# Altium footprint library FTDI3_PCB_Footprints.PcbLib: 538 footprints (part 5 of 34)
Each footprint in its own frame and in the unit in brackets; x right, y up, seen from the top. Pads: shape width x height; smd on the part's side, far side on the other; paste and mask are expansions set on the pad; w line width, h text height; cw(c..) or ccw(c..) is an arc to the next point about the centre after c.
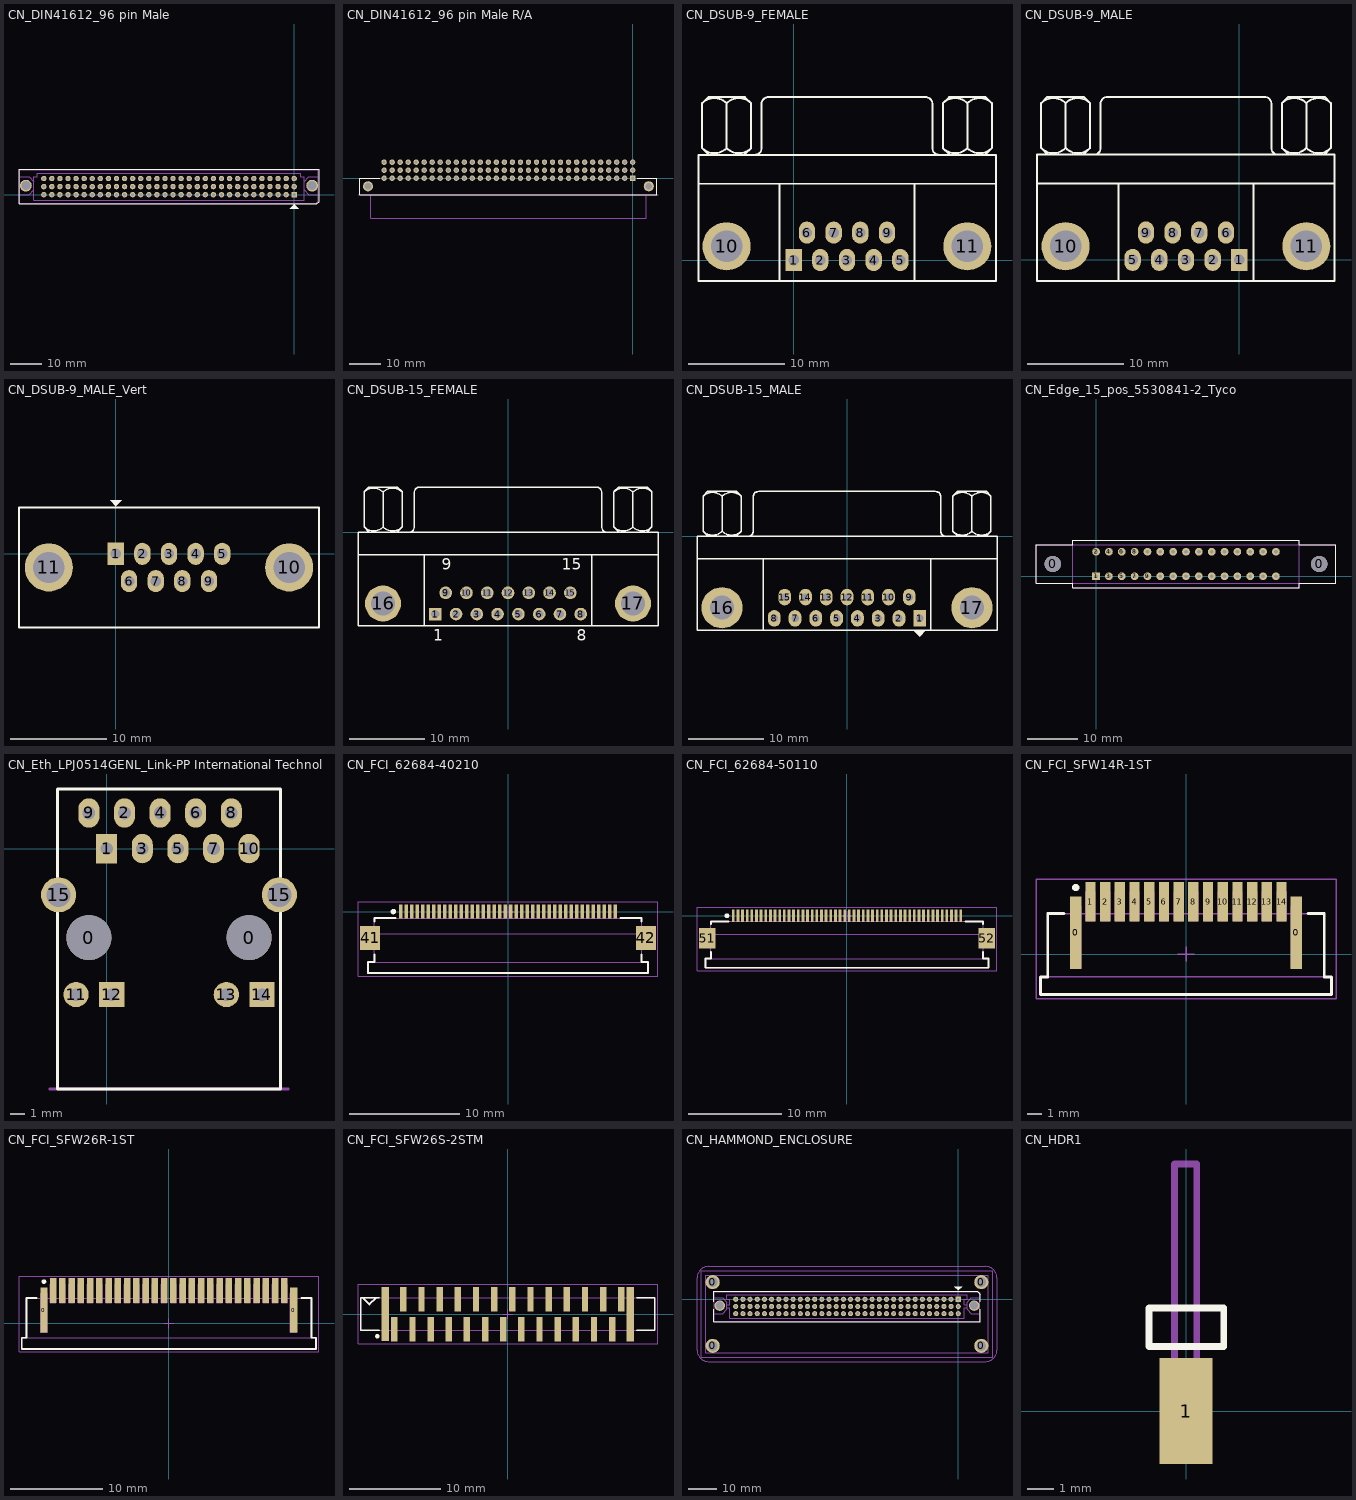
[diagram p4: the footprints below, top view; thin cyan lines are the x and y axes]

## CN_DIN41612_96 pin Male [mm] "DIN41612 series; FCI Part No. 86093967113745E1LF; Number of Positions = 95; pitch 2.54 mm"
height 15.24
pads (98):
  rect 1.7x1.7 hole 1: 1(0,0)
  round 1.7 hole 1: 2(-2.54,0) 3(-5.08,0) 4(-7.62,0) 5(-10.16,0) 6(-12.7,0) 7(-15.24,0) 8(-17.78,0) 9(-20.32,0) 10(-22.86,0) 11(-25.4,0) 12(-27.94,0) 13(-30.48,0) 14(-33.02,0) 15(-35.56,0) 16(-38.1,0) 17(-40.64,0) 18(-43.18,0) 19(-45.72,0) 20(-48.26,0) 21(-50.8,0) 22(-53.34,0) 23(-55.88,0) 24(-58.42,0) 25(-60.96,0) 26(-63.5,0) 27(-66.04,0) 28(-68.58,0) 29(-71.12,0) 30(-73.66,0) 31(-76.2,0) 32(-78.74,0) 33(0,2.54) 34(-2.54,2.54) 35(-5.08,2.54) 36(-7.62,2.54) 37(-10.16,2.54) 38(-12.7,2.54) 39(-15.24,2.54) 40(-17.78,2.54) 41(-20.32,2.54) 42(-22.86,2.54) 43(-25.4,2.54) 44(-27.94,2.54) 45(-30.48,2.54) 46(-33.02,2.54) 47(-35.56,2.54) 48(-38.1,2.54) 49(-40.64,2.54) 50(-43.18,2.54) 51(-45.72,2.54) 52(-48.26,2.54) 53(-50.8,2.54) 54(-53.34,2.54) 55(-55.88,2.54) 56(-58.42,2.54) 57(-60.96,2.54) 58(-63.5,2.54) 59(-66.04,2.54) 60(-68.58,2.54) 61(-71.12,2.54) 62(-73.66,2.54) 63(-76.2,2.54) 64(-78.74,2.54) 65(0,5.08) 66(-2.54,5.08) 67(-5.08,5.08) 68(-7.62,5.08) 69(-10.16,5.08) 70(-12.7,5.08) 71(-15.24,5.08) 72(-17.78,5.08) 73(-20.32,5.08) 74(-22.86,5.08) 75(-25.4,5.08) 76(-27.94,5.08) 77(-30.48,5.08) 78(-33.02,5.08) 79(-35.56,5.08) 80(-38.1,5.08) 81(-40.64,5.08) 82(-43.18,5.08) 83(-45.72,5.08) 84(-48.26,5.08) 85(-50.8,5.08) 86(-53.34,5.08) 87(-55.88,5.08) 88(-58.42,5.08) 89(-60.96,5.08) 90(-63.5,5.08) 91(-66.04,5.08) 92(-68.58,5.08) 93(-71.12,5.08) 94(-73.66,5.08) 95(-76.2,5.08) 96(-78.74,5.08)
  round 3.7 hole 2.8: MH1(-84.37,2.84) MH2(5.63,2.84)
Top Overlay:
  region: 0,-3.05 1.39,-4.44 -1.39,-4.44
  lines w0.254: -86.53,-2.93 7.05,-2.93 7.79,-2.19 7.79,8.01 -86.53,8.01 -86.53,-2.93
M13_Assembly_Info:
  lines w0.1: -86.35,0 -83.36,0 -81.86,1.5 ; -86.35,5.6 -83.36,5.6 -81.86,4.1 ; -81.86,4.55 -81.86,-1.69 ; -80.82,6.77 2.08,6.77 ; -80.82,6.78 -80.82,5.59 -81.86,5.59 -81.86,4.1 ; 2.08,6.78 2.08,5.59 3.12,5.59 3.12,4.1 ; 3.12,1.5 4.62,0 7.61,0 ; 3.12,4.55 3.12,-1.69 ; 7.61,5.6 4.62,5.6 3.12,4.1 ; -81.86,-1.69 3.12,-1.69 ; -81.86,-1.69 -81.86,1.4 -81.86,4.1 ; 3.12,-1.69 3.12,1.4 3.12,4.1 ; -86.35,-2.755 6.965,-2.755 7.61,-2.11 7.61,7.835 -86.35,7.835 -86.35,-2.755
  text "c32" at -80.73,6.57 h1
  text "b32" at -80.73,3.68 h1
  text "a32" at -80.72,1.05 h1
  text "a1" at 0.97,0.53 h1
  text "b1" at 0.96,3.05 h1
  text "c1" at 0.96,5.72 h1
3D body: height 11.52, standoff -3.28, extent -86.298,-2.723 7.557,7.877

## CN_DIN41612_96 pin Male R/A [mm] "DIN41612 series; FCI Part No. 86093967113745E1LF; Number of Positions = 95; pitch 2.54 mm"
height 15.24
pads (98):
  rect 1.7x1.7 hole 1: 1(0,0)
  round 1.7 hole 1: 2(-2.54,0) 3(-5.08,0) 4(-7.62,0) 5(-10.16,0) 6(-12.7,0) 7(-15.24,0) 8(-17.78,0) 9(-20.32,0) 10(-22.86,0) 11(-25.4,0) 12(-27.94,0) 13(-30.48,0) 14(-33.02,0) 15(-35.56,0) 16(-38.1,0) 17(-40.64,0) 18(-43.18,0) 19(-45.72,0) 20(-48.26,0) 21(-50.8,0) 22(-53.34,0) 23(-55.88,0) 24(-58.42,0) 25(-60.96,0) 26(-63.5,0) 27(-66.04,0) 28(-68.58,0) 29(-71.12,0) 30(-73.66,0) 31(-76.2,0) 32(-78.74,0) 33(0,2.54) 34(-2.54,2.54) 35(-5.08,2.54) 36(-7.62,2.54) 37(-10.16,2.54) 38(-12.7,2.54) 39(-15.24,2.54) 40(-17.78,2.54) 41(-20.32,2.54) 42(-22.86,2.54) 43(-25.4,2.54) 44(-27.94,2.54) 45(-30.48,2.54) 46(-33.02,2.54) 47(-35.56,2.54) 48(-38.1,2.54) 49(-40.64,2.54) 50(-43.18,2.54) 51(-45.72,2.54) 52(-48.26,2.54) 53(-50.8,2.54) 54(-53.34,2.54) 55(-55.88,2.54) 56(-58.42,2.54) 57(-60.96,2.54) 58(-63.5,2.54) 59(-66.04,2.54) 60(-68.58,2.54) 61(-71.12,2.54) 62(-73.66,2.54) 63(-76.2,2.54) 64(-78.74,2.54) 65(0,5.08) 66(-2.54,5.08) 67(-5.08,5.08) 68(-7.62,5.08) 69(-10.16,5.08) 70(-12.7,5.08) 71(-15.24,5.08) 72(-17.78,5.08) 73(-20.32,5.08) 74(-22.86,5.08) 75(-25.4,5.08) 76(-27.94,5.08) 77(-30.48,5.08) 78(-33.02,5.08) 79(-35.56,5.08) 80(-38.1,5.08) 81(-40.64,5.08) 82(-43.18,5.08) 83(-45.72,5.08) 84(-48.26,5.08) 85(-50.8,5.08) 86(-53.34,5.08) 87(-55.88,5.08) 88(-58.42,5.08) 89(-60.96,5.08) 90(-63.5,5.08) 91(-66.04,5.08) 92(-68.58,5.08) 93(-71.12,5.08) 94(-73.66,5.08) 95(-76.2,5.08) 96(-78.74,5.08)
  round 3.2 hole 2.1: MH1(-83.82,-2.54) MH2(5.08,-2.54)
Top Overlay:
  lines w0.2: -80.1,0 -86.37,0 -86.37,-5.3 7.63,-5.3 7.63,0 1.41,0
Mechanical 1:
  lines w0.2: -87,-5.3 8,-5.3
M13_Assembly_Info:
  lines w0.2: -82.97,-5.3 -82.97,-12.74 4.23,-12.74 4.23,-5.3
  text "c32" at -80.8,6.49 h1
  text "b32" at -80.8,3.71 h1
  text "a32" at -80.81,1.04 h1
  text "a1" at 1.07,0.56 h1
  text "b1" at 1.04,3.13 h1
  text "c1" at 1,5.64 h1

## CN_DSUB-9_FEMALE [mm] "Connector; D Subminiature AMPLIMITE 2000; 9 Position; Right Angle"
height 12.75
pads (11):
  rect 1.7x2.3 hole 1.09: 1(0,0)
  oval 1.7x2.3 hole 1.09: 2(2.77,0) 3(5.54,0) 4(8.31,0) 5(11.08,0) 6(1.385,2.84) 7(4.155,2.84) 8(6.925,2.84) 9(9.695,2.84)
  round 5 hole 3.26: 10(-6.955,1.42) 11(18.035,1.42)
Top Overlay:
  lines w0.2: -9.86,7.92 20.94,7.92 ; -9.498,16.27 -9.498,11.619 -8.863,10.984 ; -9.498,16.285 -8.863,16.92 -5.053,16.92 -4.418,16.285 ; -6.958,11.619 -6.958,16.27 ; -5.053,10.984 -4.418,11.619 -4.418,16.27 ; -4.418,15.006 -4.418,15.218 ; -4.02,10.925 ccw(c-4.02,11.62) -3.325,11.62 -3.325,16.22 ; -3.32,16.225 cw(c-2.625,16.225) -2.625,16.92 13.705,16.92 cw(c13.705,16.225) 14.4,16.225 ; -1.46,-2.175 -1.46,7.92 ; 12.54,-2.175 12.54,7.92 ; 14.405,16.22 14.405,11.62 ccw(c15.1,11.62) 15.1,10.925 ; 15.502,16.27 15.502,11.619 16.137,10.984 ; 15.502,16.285 16.137,16.92 19.947,16.92 20.582,16.285 ; 18.042,11.619 18.042,16.27 ; 19.947,10.984 20.582,11.619 20.582,16.27 ; 20.582,15.006 20.582,15.218 ; -9.86,-2.175 21.025,-2.175 21.025,10.92 -9.86,10.92 -9.86,-2.175
  lines w0.203: -9.5,11.617 ccw(c-8.228,12.889) -6.956,11.617 ; -9.498,16.27 cw(c-8.226,14.998) -6.953,16.27 ; -6.962,16.27 cw(c-5.69,14.998) -4.418,16.27 ; -6.96,11.617 ccw(c-5.688,12.889) -4.416,11.617 ; 15.5,11.617 ccw(c16.772,12.889) 18.044,11.617 ; 15.502,16.27 cw(c16.774,14.998) 18.047,16.27 ; 18.038,16.27 cw(c19.31,14.998) 20.582,16.27 ; 18.04,11.617 ccw(c19.312,12.889) 20.584,11.617
3D body: height 12.44, standoff 0.02, extent -9.975,-2.275 21.125,16.715

## CN_DSUB-9_MALE [mm] "Connector; D Subminiature AMPLIMITE 2000; 9 Position; Right Angle"
height 12.75
pads (11):
  rect 1.7x2.3 hole 1.09: 1(0,0)
  oval 1.7x2.3 hole 1.09: 2(-2.77,0) 3(-5.54,0) 4(-8.31,0) 5(-11.08,0) 6(-1.385,2.84) 7(-4.155,2.84) 8(-6.925,2.84) 9(-9.695,2.84)
  round 5 hole 3.26: 10(-18.035,1.42) 11(6.955,1.42)
Top Overlay:
  lines w0.2: -20.94,7.92 9.86,7.92 ; -20.578,16.27 -20.578,11.619 -19.943,10.984 ; -20.578,16.285 -19.943,16.92 -16.133,16.92 -15.498,16.285 ; -18.038,11.619 -18.038,16.27 ; -16.133,10.984 -15.498,11.619 -15.498,16.27 ; -15.498,15.006 -15.498,15.218 ; -15.1,10.925 ccw(c-15.1,11.62) -14.405,11.62 -14.405,16.22 ; -14.4,16.225 cw(c-13.705,16.225) -13.705,16.92 2.625,16.92 cw(c2.625,16.225) 3.32,16.225 ; -12.54,-2.2 -12.54,7.92 ; 1.46,-2.2 1.46,7.92 ; 3.325,16.22 3.325,11.62 ccw(c4.02,11.62) 4.02,10.925 ; 4.422,16.27 4.422,11.619 5.057,10.984 ; 4.422,16.285 5.057,16.92 8.867,16.92 9.502,16.285 ; 6.962,11.619 6.962,16.27 ; 8.867,10.984 9.502,11.619 9.502,16.27 ; 9.502,15.006 9.502,15.218 ; -21.025,-2.2 9.875,-2.2 9.875,10.92 -21.025,10.92 -21.025,-2.2
  lines w0.203: -20.58,11.617 ccw(c-19.308,12.889) -18.036,11.617 ; -20.578,16.27 cw(c-19.306,14.998) -18.033,16.27 ; -18.042,16.27 cw(c-16.77,14.998) -15.498,16.27 ; -18.04,11.617 ccw(c-16.768,12.889) -15.496,11.617 ; 4.42,11.617 ccw(c5.692,12.889) 6.964,11.617 ; 4.422,16.27 cw(c5.694,14.998) 6.967,16.27 ; 6.958,16.27 cw(c8.23,14.998) 9.502,16.27 ; 6.96,11.617 ccw(c8.232,12.889) 9.504,11.617
3D body: height 12.44, standoff 0.02, extent -21.125,-2.3 9.975,16.98

## CN_DSUB-9_MALE_Vert [mm] "Connector; D Subminiature AMPLIMITE 2000; 9 Position; Vertical"
height 12.75
pads (11):
  rect 1.7x2.3 hole 1.09: 1(0,0)
  oval 1.7x2.3 hole 1.09: 2(2.77,0) 3(5.54,0) 4(8.31,0) 5(11.08,0) 6(1.385,-2.84) 7(4.155,-2.84) 8(6.925,-2.84) 9(9.695,-2.84)
  round 5 hole 3.26: 10(18.035,-1.42) 11(-6.955,-1.42)
Top Overlay:
  region: 0.015,4.95 0.614,5.55 -0.589,5.55
  lines w0.2: -10.06,-7.67 21.14,-7.67 21.14,4.83 -10.06,4.83 -10.06,-7.67

## CN_DSUB-15_FEMALE [mm] "Connector; D Subminiature; 15 Position; Right Angle; Female"
height 12.75
pads (17):
  rect 1.69x1.69 hole 1.09: 1(-9.695,-10.92)
  round 1.69 hole 1.09: 2(-6.925,-10.92) 3(-4.155,-10.92) 4(-1.385,-10.92) 5(1.385,-10.92) 6(4.155,-10.92) 7(6.925,-10.92) 8(9.695,-10.92) 9(-8.31,-8.08) 10(-5.54,-8.08) 11(-2.77,-8.08) 12(0,-8.08) 13(2.77,-8.08) 14(5.54,-8.08) 15(8.31,-8.08)
  round 4.8 hole 3.18: 16(-16.66,-9.5) 17(16.66,-9.5)
Top Overlay:
  lines w0.2: -20,-3 20,-3 ; -19.188,5.35 -19.188,0.699 -18.553,0.064 ; -19.188,5.365 -18.553,6 -14.743,6 -14.108,5.365 ; -16.648,0.699 -16.648,5.35 ; -14.743,0.064 -14.108,0.699 -14.108,5.35 ; -14.108,4.086 -14.108,4.298 ; -13.195,0.005 ccw(c-13.195,0.7) -12.5,0.7 -12.5,5.3 ; -12.495,5.305 cw(c-11.8,5.305) -11.8,6 11.8,6 cw(c11.8,5.305) 12.495,5.305 ; -11.14,-12.5 -11.14,-3 ; 11.14,-12.5 11.14,-3 ; 12.5,5.3 12.5,0.7 ccw(c13.195,0.7) 13.195,0.005 ; 14.112,5.35 14.112,0.699 14.747,0.064 ; 14.112,5.365 14.747,6 18.557,6 19.192,5.365 ; 16.652,0.699 16.652,5.35 ; 18.557,0.064 19.192,0.699 19.192,5.35 ; 19.192,4.086 19.192,4.298 ; -20,-12.5 20,-12.5 20,0 -20,0 -20,-12.5
  lines w0.203: -19.19,0.697 ccw(c-17.918,1.969) -16.646,0.697 ; -19.188,5.35 cw(c-17.916,4.078) -16.643,5.35 ; -16.652,5.35 cw(c-15.38,4.078) -14.108,5.35 ; -16.65,0.697 ccw(c-15.378,1.969) -14.106,0.697 ; 14.11,0.697 ccw(c15.382,1.969) 16.654,0.697 ; 14.112,5.35 cw(c15.384,4.078) 16.657,5.35 ; 16.648,5.35 cw(c17.92,4.078) 19.192,5.35 ; 16.65,0.697 ccw(c17.922,1.969) 19.194,0.697
  text "9" at -8.81,-4.975 h1.5
  text "15" at 7.185,-4.975 h1.5
  text "8" at 9.195,-14.475 h1.5
  text "1" at -9.945,-14.475 h1.5

## CN_DSUB-15_MALE [mm] "Connector; D Subminiature; 15 Position; Right Angle; Male"
height 12.75
pads (17):
  rect 1.7x2.2 hole 1: 1(9.695,-10.92)
  oval 1.7x2.2 hole 1: 2(6.925,-10.92) 3(4.155,-10.92) 4(1.385,-10.92) 5(-1.385,-10.92) 6(-4.155,-10.92) 7(-6.925,-10.92) 8(-9.695,-10.92) 9(8.31,-8.08) 10(5.54,-8.08) 11(2.77,-8.08) 12(0,-8.08) 13(-2.77,-8.08) 14(-5.54,-8.08) 15(-8.31,-8.08)
  round 5.5 hole 3.2: 16(-16.66,-9.5) 17(16.66,-9.5)
Top Overlay:
  region: 10.53,-12.515 9.7,-13.345 9.69,-13.345 8.85,-12.505
  lines w0.2: -20,-3 20,-3 ; -19.188,5.35 -19.188,0.699 -18.553,0.064 ; -19.188,5.365 -18.553,6 -14.743,6 -14.108,5.365 ; -16.648,0.699 -16.648,5.35 ; -14.743,0.064 -14.108,0.699 -14.108,5.35 ; -14.108,4.086 -14.108,4.298 ; -13.195,0.005 ccw(c-13.195,0.7) -12.5,0.7 -12.5,5.3 ; -12.495,5.305 cw(c-11.8,5.305) -11.8,6 11.8,6 cw(c11.8,5.305) 12.495,5.305 ; -11.14,-12.5 -11.14,-3 ; 11.14,-12.5 11.14,-3 ; 12.5,5.3 12.5,0.7 ccw(c13.195,0.7) 13.195,0.005 ; 14.112,5.35 14.112,0.699 14.747,0.064 ; 14.112,5.365 14.747,6 18.557,6 19.192,5.365 ; 16.652,0.699 16.652,5.35 ; 18.557,0.064 19.192,0.699 19.192,5.35 ; 19.192,4.086 19.192,4.298 ; -20,-12.5 20,-12.5 20,0 -20,0 -20,-12.5
  lines w0.203: -19.19,0.697 ccw(c-17.918,1.969) -16.646,0.697 ; -19.188,5.35 cw(c-17.916,4.078) -16.643,5.35 ; -16.652,5.35 cw(c-15.38,4.078) -14.108,5.35 ; -16.65,0.697 ccw(c-15.378,1.969) -14.106,0.697 ; 14.11,0.697 ccw(c15.382,1.969) 16.654,0.697 ; 14.112,5.35 cw(c15.384,4.078) 16.657,5.35 ; 16.648,5.35 cw(c17.92,4.078) 19.192,5.35 ; 16.65,0.697 ccw(c17.922,1.969) 19.194,0.697

## CN_Edge_15_pos_5530841-2_Tyco [mil] "Card Edge connector; 15 pos; 0.1\" (2.54mm) pitch; 5530841-2 Tyco Electronics Corporation"
height 609.84
pads (32):
  round 127.95 hole 127.95 unplated: 0(-337.4,95.47) 0(1737.4,95.47)
  rect 60x60 hole 30: 1(0,0)
  round 60 hole 30: 2(0,190.94) 3(100,0) 4(100,190.94) 5(200,0) 6(200,190.94) 7(300,0) 8(300,190.94) 9(400,0) 10(400,190.94) 11(500,0) 12(500,190.94) 13(600,0) 14(600,190.94) 15(700,0) 16(700,190.94) 17(800,0) 18(800,190.94) 19(900,0) 20(900,190.94) 21(1000,0) 22(1000,190.94) 23(1100,0) 24(1100,190.94) 25(1200,0) 26(1200,190.94) 27(1300,0) 28(1300,190.94) 29(1400,0) 30(1400,190.94)
Top Overlay:
  lines w7.87: -467.72,-54.72 -467.72,245.67 -179.92,245.67 -179.92,279.53 1579.92,279.53 1579.92,245.67 1867.72,245.67 1867.72,-54.72 1579.92,-54.72 1579.92,-88.58 -179.92,-88.58 -179.92,-54.72 -467.72,-54.72
M13_Assembly_Info:
  lines w3.94: -467.52,-54.53 1867.52,-54.53 1867.52,245.47 -467.52,245.47 -467.52,-54.53 ; -179.92,-88.58 1579.92,-88.58 1579.92,279.53 -179.92,279.53 -179.92,-88.58
3D body: height 250, standoff 0, extent -467.52,-54.53 1867.52,245.47

## CN_Eth_LPJ0514GENL_Link-PP International Technology [mm] "RJ45 Ethernet Connector; PoE compatible; with magnetics and LEDs; Link-PP International Technology Co. Ltd."
height 13.4
pads (18):
  round 3.2 hole 3.2 unplated: 0(-1.27,-6.35) 0(10.16,-6.35)
  rect 1.5x2.1 hole 0.9: 1(0,0)
  oval 1.5x2.1 hole 0.9: 2(1.27,2.54) 3(2.54,0) 4(3.81,2.54) 5(5.08,0) 6(6.35,2.54) 7(7.62,0) 8(8.89,2.54) 9(-1.27,2.54) 10(10.16,0)
  round 1.8 hole 0.9: 11(-2.185,-10.414) 13(8.535,-10.414)
  rect 1.8x1.8 hole 0.9: 12(0.355,-10.414) 14(11.075,-10.414)
  round 2.5 hole 1.7: 15(-3.43,-3.302) 15(12.32,-3.302)
Top Overlay:
  lines w0.2: -3.505,-17.145 12.395,-17.145 12.395,4.25 -3.505,4.25 -3.505,-17.145
M13_Assembly_Info:
  lines w0.2: -4.055,-17.15 12.945,-17.15
  text "A" at -2.49,-9.449 h0.9
  text "K" at 0.075,-9.449 h0.9
  text "K" at 10.795,-9.449 h0.9
  text "A" at 8.23,-9.449 h0.9
  text "Yellow" at 8.231,-12.395 h0.9
  text "Green" at -2.489,-12.395 h0.9
3D body: height 13.5, standoff 0, extent -3.505,-17.145 12.395,4.25

## CN_FCI_62684-40210 [mm] "FPC/FFC Connector; 62684-40210; 40 Positions; 0.5mm Pitch Top Contact; FCI"
height 2
pads (42):
  rect 0.3x1.3 smd: 1(-9.75,0) 2(-9.25,0) 3(-8.75,0) 4(-8.25,0) 5(-7.75,0) 6(-7.25,0) 7(-6.75,0) 8(-6.25,0) 9(-5.75,0) 10(-5.25,0) 11(-4.75,0) 12(-4.25,0) 13(-3.75,0) 14(-3.25,0) 15(-2.75,0) 16(-2.25,0) 17(-1.75,0) 18(-1.25,0) 19(-0.75,0) 20(-0.25,0) 21(0.25,0) 22(0.75,0) 23(1.25,0) 24(1.75,0) 25(2.25,0) 26(2.75,0) 27(3.25,0) 28(3.75,0) 29(4.25,0) 30(4.75,0) 31(5.25,0) 32(5.75,0) 33(6.25,0) 34(6.75,0) 35(7.25,0) 36(7.75,0) 37(8.25,0) 38(8.75,0) 39(9.25,0) 40(9.75,0)
  rect 1.8x2.2 smd: 41(-12.55,-2.4) 42(12.55,-2.4)
Top Overlay:
  circle w0.25: c-10.425,0 r0.125
  lines w0.2: -12.15,-3.9 -12.15,-4.6 -12.75,-4.6 -12.75,-5.6 12.75,-5.6 12.75,-4.6 12.15,-4.6 12.15,-3.9 ; -12.15,-0.9 -12.15,-0.6 -10.25,-0.6 ; 10.25,-0.6 12.15,-0.6 12.15,-0.9
M13_Assembly_Info:
  lines w0.1: -12.15,-2 12.15,-2 ; -12.15,-4.6 -12.15,-0.6 12.15,-0.6 12.15,-4.6 12.75,-4.6 ; -12.15,-4.6 -12.75,-4.6 -12.75,-5.6 12.75,-5.6 12.75,-4.6 ; -12.15,-4.6 12.75,-4.6
  lines w0.2: -12.15,-2.9 -12.75,-2.9 -12.75,-1.9 -12.15,-1.9 ; 12.19,-2.9 12.79,-2.9 12.79,-1.9 12.19,-1.9
M15_Country_Yard:
  lines w0.1: -13.65,-5.9 -13.65,0.9 13.64,0.9 13.64,-5.9 -13.65,-5.9 ; -0.55,0 0.55,0 -0.55,0 ; 0,-0.5 0,0.5 0,-0.5
3D body: height 0, standoff 0, extent -12.75,-5.6 12.75,-0.6

## CN_FCI_62684-50110 [mm] "FPC/FFC Connector; 62684-50110; 50 Position; 0.5mm Spaced Bottom Contact; FCI"
height 2
pads (52):
  rect 0.3x1.3 smd: 1(-12.25,0) 2(-11.75,0) 3(-11.25,0) 4(-10.75,0) 5(-10.25,0) 6(-9.75,0) 7(-9.25,0) 8(-8.75,0) 9(-8.25,0) 10(-7.75,0) 11(-7.25,0) 12(-6.75,0) 13(-6.25,0) 14(-5.75,0) 15(-5.25,0) 16(-4.75,0) 17(-4.25,0) 18(-3.75,0) 19(-3.25,0) 20(-2.75,0) 21(-2.25,0) 22(-1.75,0) 23(-1.25,0) 24(-0.75,0) 25(-0.25,0) 26(0.25,0) 27(0.75,0) 28(1.25,0) 29(1.75,0) 30(2.25,0) 31(2.75,0) 32(3.25,0) 33(3.75,0) 34(4.25,0) 35(4.75,0) 36(5.25,0) 37(5.75,0) 38(6.25,0) 39(6.75,0) 40(7.25,0) 41(7.75,0) 42(8.25,0) 43(8.75,0) 44(9.25,0) 45(9.75,0) 46(10.25,0) 47(10.75,0) 48(11.25,0) 49(11.75,0) 50(12.25,0)
  rect 1.8x2.2 smd: 51(-15.05,-2.4) 52(15.05,-2.4)
Top Overlay:
  circle w0.25: c-12.925,0 r0.125
  lines w0.2: -14.65,-3.9 -14.65,-4.6 -15.25,-4.6 -15.25,-5.6 15.25,-5.6 15.25,-4.6 14.65,-4.6 14.65,-3.9 ; -14.65,-0.9 -14.65,-0.6 -12.75,-0.6 ; 12.75,-0.6 14.65,-0.6 14.65,-0.9
M13_Assembly_Info:
  lines w0.1: -14.65,-2 14.65,-2 ; -12.75,-2 12.75,-2 ; -14.65,-4.6 -14.65,-0.6 14.65,-0.6 14.65,-4.6 ; -14.65,-4.6 -15.25,-4.6 -15.25,-5.6 15.25,-5.6 15.25,-4.6 14.65,-4.6 ; -14.65,-4.6 14.65,-4.6
  lines w0.2: -14.65,-2.9 -15.25,-2.9 -15.25,-1.9 -14.65,-1.9 ; 14.65,-2.9 15.25,-2.9 15.25,-1.9 14.65,-1.9
M15_Country_Yard:
  lines w0.1: -0.55,0 0.55,0 ; 0,-0.5 0,0.5 ; -16.15,-5.9 -16.15,0.9 16.15,0.9 16.15,-5.9 -16.15,-5.9
3D body: height 0, standoff 0, extent -15.25,-5.6 15.25,-0.6

## CN_FCI_SFW14R-1ST [mm] "FPC/FFC Connector; SFW14R-1ST; 14 Positions; 1.0mm Spaced Bottom Contact; FCI"
height 2
pads (16):
  rect 0.8x4.9 smd: 0(-7.5,1.45) 0(7.5,1.45)
  rect 0.7x2.7 smd: 1(-6.5,3.55) 2(-5.5,3.55) 3(-4.5,3.55) 4(-3.5,3.55) 5(-2.5,3.55) 6(-1.5,3.55) 7(-0.5,3.55) 8(0.5,3.55) 9(1.5,3.55) 10(2.5,3.55) 11(3.5,3.55) 12(4.5,3.55) 13(5.5,3.55) 14(6.5,3.55)
Top Overlay:
  circle w0.25: c-7.5,4.525 r0.125
  lines w0.2: -8.3,2.75 -9.4,2.75 -9.4,-1.55 -9.9,-1.55 -9.9,-2.75 9.9,-2.75 9.9,-1.55 9.4,-1.55 9.4,2.75 8.3,2.75
M13_Assembly_Info:
  lines w0.1: -9.4,-1.55 -9.4,2.75 9.4,2.75 9.4,-1.55 ; -9.9,-2.75 -9.9,-1.55 9.9,-1.55 9.9,-2.75 -9.9,-2.75 ; -7.85,-0.95 -7.85,3.25 -7.15,3.25 -7.15,-0.95 -7.85,-0.95 ; -6.8,2.25 -6.8,4.25 -6.2,4.25 -6.2,2.25 -6.8,2.25 ; -5.8,2.25 -5.2,2.25 -5.2,4.25 -5.8,4.25 -5.8,2.25 ; -4.8,2.25 -4.2,2.25 -4.2,4.25 -4.8,4.25 -4.8,2.25 ; -3.8,2.25 -3.2,2.25 -3.2,4.25 -3.8,4.25 -3.8,2.25 ; -2.8,2.25 -2.2,2.25 -2.2,4.25 -2.8,4.25 -2.8,2.25 ; -1.8,2.25 -1.2,2.25 -1.2,4.25 -1.8,4.25 -1.8,2.25 ; -0.8,2.25 -0.2,2.25 -0.2,4.25 -0.8,4.25 -0.8,2.25 ; 0.2,2.25 0.2,4.25 0.8,4.25 0.8,2.25 0.2,2.25 ; 1.2,2.25 1.2,4.25 1.8,4.25 1.8,2.25 1.2,2.25 ; 2.2,2.25 2.2,4.25 2.8,4.25 2.8,2.25 2.2,2.25 ; 3.2,2.25 3.2,4.25 3.8,4.25 3.8,2.25 3.2,2.25 ; 4.2,2.25 4.2,4.25 4.8,4.25 4.8,2.25 4.2,2.25 ; 5.2,2.25 5.2,4.25 5.8,4.25 5.8,2.25 5.2,2.25 ; 6.2,2.25 6.8,2.25 6.8,4.25 6.2,4.25 6.2,2.25 ; 7.15,-0.95 7.85,-0.95 7.85,3.25 7.15,3.25 7.15,-0.95
M15_Country_Yard:
  lines w0.1: -0.55,0 0.55,0 ; 0,-0.5 0,0.5 ; -10.2,-3.05 -10.2,5.1 10.2,5.1 10.2,-3.05 -10.2,-3.05
3D body: height 0, standoff 0, extent -9.9,-2.75 9.9,2.75

## CN_FCI_SFW26R-1ST [mm] "FPC/FFC Connector; SFW26R-1ST; 26 Positions; 1.0mm Spaced Bottom Contact; FCI"
height 2
pads (28):
  rect 0.8x4.9 smd: 0(-13.5,1.45) 0(13.5,1.45)
  rect 0.7x2.7 smd: 1(-12.5,3.55) 2(-11.5,3.55) 3(-10.5,3.55) 4(-9.5,3.55) 5(-8.5,3.55) 6(-7.5,3.55) 7(-6.5,3.55) 8(-5.5,3.55) 9(-4.5,3.55) 10(-3.5,3.55) 11(-2.5,3.55) 12(-1.5,3.55) 13(-0.5,3.55) 14(0.5,3.55) 15(1.5,3.55) 16(2.5,3.55) 17(3.5,3.55) 18(4.5,3.55) 19(5.5,3.55) 20(6.5,3.55) 21(7.5,3.55) 22(8.5,3.55) 23(9.5,3.55) 24(10.5,3.55) 25(11.5,3.55) 26(12.5,3.55)
Top Overlay:
  circle w0.25: c-13.5,4.525 r0.125
  lines w0.2: -14.3,2.75 -15.4,2.75 -15.4,-1.55 -15.9,-1.55 -15.9,-2.75 15.925,-2.75 15.925,-1.55 15.425,-1.55 15.425,2.75 14.325,2.75
M13_Assembly_Info:
  lines w0.1: -15.4,-1.55 -15.4,2.75 15.425,2.75 15.425,-1.55 ; -15.9,-2.75 15.925,-2.75 15.925,-1.55 -15.9,-1.55 -15.9,-2.75 ; -13.85,-0.95 -13.15,-0.95 -13.15,3.25 -13.85,3.25 -13.85,-0.95 ; -12.8,2.25 -12.2,2.25 -12.2,4.25 -12.8,4.25 -12.8,2.25 ; -11.8,2.25 -11.8,4.25 -11.2,4.25 -11.2,2.25 -11.8,2.25 ; -10.8,2.25 -10.8,4.25 -10.2,4.25 -10.2,2.25 -10.8,2.25 ; -9.8,2.25 -9.8,4.25 -9.2,4.25 -9.2,2.25 -9.8,2.25 ; -8.8,2.25 -8.8,4.25 -8.2,4.25 -8.2,2.25 -8.8,2.25 ; -7.8,2.25 -7.8,4.25 -7.2,4.25 -7.2,2.25 -7.8,2.25 ; -6.8,2.25 -6.8,4.25 -6.2,4.25 -6.2,2.25 -6.8,2.25 ; -5.8,2.25 -5.2,2.25 -5.2,4.25 -5.8,4.25 -5.8,2.25 ; -4.8,2.25 -4.2,2.25 -4.2,4.25 -4.8,4.25 -4.8,2.25 ; -3.8,2.25 -3.2,2.25 -3.2,4.25 -3.8,4.25 -3.8,2.25 ; -2.8,2.25 -2.2,2.25 -2.2,4.25 -2.8,4.25 -2.8,2.25 ; -1.8,2.25 -1.2,2.25 -1.2,4.25 -1.8,4.25 -1.8,2.25 ; -0.8,2.25 -0.2,2.25 -0.2,4.25 -0.8,4.25 -0.8,2.25 ; 0.2,2.25 0.2,4.25 0.8,4.25 0.8,2.25 0.2,2.25 ; 1.2,2.25 1.8,2.25 1.8,4.25 1.2,4.25 1.2,2.25 ; 2.2,2.25 2.8,2.25 2.8,4.25 2.2,4.25 2.2,2.25 ; 3.2,2.25 3.8,2.25 3.8,4.25 3.2,4.25 3.2,2.25 ; 4.2,2.25 4.8,2.25 4.8,4.25 4.2,4.25 4.2,2.25 ; 5.2,2.25 5.8,2.25 5.8,4.25 5.2,4.25 5.2,2.25 ; 6.2,2.25 6.2,4.25 6.8,4.25 6.8,2.25 6.2,2.25 ; 7.2,2.25 7.2,4.25 7.8,4.25 7.8,2.25 7.2,2.25 ; 8.2,2.25 8.2,4.25 8.8,4.25 8.8,2.25 8.2,2.25 ; 9.2,2.25 9.2,4.25 9.8,4.25 9.8,2.25 9.2,2.25 ; 10.2,2.25 10.2,4.25 10.8,4.25 10.8,2.25 10.2,2.25 ; 11.2,2.25 11.2,4.25 11.8,4.25 11.8,2.25 11.2,2.25 ; 12.2,2.25 12.8,2.25 12.8,4.25 12.2,4.25 12.2,2.25 ; 13.15,-0.95 13.85,-0.95 13.85,3.25 13.15,3.25 13.15,-0.95
M15_Country_Yard:
  lines w0.1: -0.55,0 0.55,0 ; 0,-0.5 0,0.5 ; -16.2,-3.05 16.25,-3.05 16.25,5.1 -16.2,5.1 -16.2,-3.05

## CN_FCI_SFW26S-2STM [mm] "FPC/FFC Connector; SFW26R-1ST; 26 Positions; 1.0mm Spaced; Straight; FCI"
height 2
pads (28):
  rect 0.8x6 smd: 0(-13.5,0) 0(13.5,-0.01)
  rect 0.7x2.7 smd: 1(-12.5,-1.66) 2(-11.5,1.65) 3(-10.5,-1.66) 4(-9.5,1.65) 5(-8.5,-1.66) 6(-7.5,1.65) 7(-6.5,-1.66) 8(-5.5,1.65) 9(-4.5,-1.66) 10(-3.5,1.65) 11(-2.5,-1.66) 12(-1.5,1.65) 13(-0.5,-1.66) 14(0.5,1.65) 15(1.5,-1.66) 16(2.5,1.65) 17(3.5,-1.66) 18(4.5,1.65) 19(5.5,-1.66) 20(6.5,1.65) 21(7.5,-1.66) 22(8.5,1.65) 23(9.5,-1.66) 24(10.5,1.65) 25(11.5,-1.66) 26(12.5,1.65)
Top Overlay:
  circle w0.25: c-14.355,-2.45 r0.125
  lines w0.2: -15.99,1.8 -15.25,1.06 ; -14.51,1.8 -15.25,1.06 ; -14.2,-1.8 -16.2,-1.8 -16.2,1.8 -14.2,1.8 ; 14.2,-1.8 16.2,-1.8 16.2,1.8 14.2,1.8 ; -15.25,1.06 -15.25,1.06
M13_Assembly_Info:
  lines w0.1: -16,1.8 -15.25,1.05 -14.5,1.8 ; -16.2,-1.8 16.2,-1.8 16.2,1.8 -16.2,1.8 -16.2,-1.8
M15_Country_Yard:
  lines w0.1: -0.55,0 0.55,0 ; 0,-0.5 0,0.5 ; -16.5,-3.25 -16.5,3.25 16.55,3.25 16.55,-3.25 -16.5,-3.25
3D body: height 0, standoff 0, extent -16.2,-1.8 16.2,1.8

## CN_HAMMOND_ENCLOSURE [mm] "96-pin DIN connector with Hammond eclosure outline"
pads (102):
  round 5 hole 3.5: 0(-86.878,-16.463) 0(-86.878,6.057) 0(8.142,-16.463) 0(8.142,6.057)
  rect 1.8x1.8 hole 1: 1(0,0)
  round 1.8 hole 1: 2(-2.54,0) 3(-5.08,0) 4(-7.62,0) 5(-10.16,0) 6(-12.7,0) 7(-15.24,0) 8(-17.78,0) 9(-20.32,0) 10(-22.86,0) 11(-25.4,0) 12(-27.94,0) 13(-30.48,0) 14(-33.02,0) 15(-35.56,0) 16(-38.1,0) 17(-40.64,0) 18(-43.18,0) 19(-45.72,0) 20(-48.26,0) 21(-50.8,0) 22(-53.34,0) 23(-55.88,0) 24(-58.42,0) 25(-60.96,0) 26(-63.5,0) 27(-66.04,0) 28(-68.58,0) 29(-71.12,0) 30(-73.66,0) 31(-76.2,0) 32(-78.74,0) 33(0,-2.54) 34(-2.54,-2.54) 35(-5.08,-2.54) 36(-7.62,-2.54) 37(-10.16,-2.54) 38(-12.7,-2.54) 39(-15.24,-2.54) 40(-17.78,-2.54) 41(-20.32,-2.54) 42(-22.86,-2.54) 43(-25.4,-2.54) 44(-27.94,-2.54) 45(-30.48,-2.54) 46(-33.02,-2.54) 47(-35.56,-2.54) 48(-38.1,-2.54) 49(-40.64,-2.54) 50(-43.18,-2.54) 51(-45.72,-2.54) 52(-48.26,-2.54) 53(-50.8,-2.54) 54(-53.34,-2.54) 55(-55.88,-2.54) 56(-58.42,-2.54) 57(-60.96,-2.54) 58(-63.5,-2.54) 59(-66.04,-2.54) 60(-68.58,-2.54) 61(-71.12,-2.54) 62(-73.66,-2.54) 63(-76.2,-2.54) 64(-78.74,-2.54) 65(0,-5.08) 66(-2.54,-5.08) 67(-5.08,-5.08) 68(-7.62,-5.08) 69(-10.16,-5.08) 70(-12.7,-5.08) 71(-15.24,-5.08) 72(-17.78,-5.08) 73(-20.32,-5.08) 74(-22.86,-5.08) 75(-25.4,-5.08) 76(-27.94,-5.08) 77(-30.48,-5.08) 78(-33.02,-5.08) 79(-35.56,-5.08) 80(-38.1,-5.08) 81(-40.64,-5.08) 82(-43.18,-5.08) 83(-45.72,-5.08) 84(-48.26,-5.08) 85(-50.8,-5.08) 86(-53.34,-5.08) 87(-55.88,-5.08) 88(-58.42,-5.08) 89(-60.96,-5.08) 90(-63.5,-5.08) 91(-66.04,-5.08) 92(-68.58,-5.08) 93(-71.12,-5.08) 94(-73.66,-5.08) 95(-76.2,-5.08) 96(-78.74,-5.08)
  round 3.7 hole 2.8: MH1(-84.37,-2.24) MH2(5.63,-2.24)
Top Overlay:
  region: -0.018,3.127 -1.408,4.517 1.372,4.517
  lines w0.254: -86.53,-3.54 -86.53,-8.01 7.79,-8.01 7.79,-3.54 ; -86.53,-0.84 -86.53,2.93 6.63,2.93 7.79,1.77 7.79,-0.84
M13_Assembly_Info:
  lines w0.1: -86.35,-5.08 -83.36,-5.08 -81.86,-3.58 -81.86,-0.98 -83.36,0.52 -86.35,0.52 ; -81.87,-1.98 -80.83,-1.98 ; -81.86,-3.08 -80.82,-3.08 -80.82,-6.77 2.08,-6.77 2.08,-3.08 3.12,-3.08 ; -80.82,-1.98 -80.82,0.01 -81.86,0.01 -81.86,1.69 3.12,1.69 3.12,0.01 2.08,0.01 2.08,-1.98 ; 2.09,-1.98 3.12,-1.98 ; 7.61,-5.08 4.62,-5.08 3.12,-3.58 3.12,-0.98 4.62,0.52 7.61,0.52 ; -86.35,-7.835 7.61,-7.835 7.61,2.25 7.105,2.755 -86.35,2.755 -86.35,-7.835
  text "c32" at -80.73,-4.39 h1
  text "b32" at -80.73,-1.4 h1
  text "a32" at -80.74,1.57 h1
  text "a1" at 0.97,0.59 h1
  text "b1" at 0.96,-2.03 h1
  text "c1" at 0.96,-4.52 h1
M15_Country_Yard:
  lines w0.2: -92.433,-18.016 -92.433,7.608 cw(c-88.433,7.608) -88.433,11.608 ; -92.428,-18.016 ccw(c-88.428,-18.016) -88.428,-22.016 ; -88.433,11.611 9.694,11.611 cw(c9.694,7.611) 13.694,7.611 ; -88.428,-22.019 9.694,-22.019 ccw(c9.694,-18.019) 13.694,-18.019 ; 13.697,-18.019 13.697,7.611 ; -90.869,-20.454 12.131,-20.454 12.131,10.046 -90.869,10.046 -90.869,-20.454 ; -89.369,-18.956 10.631,-18.956 10.631,8.544 -89.369,8.544 -89.369,-18.956
3D body: height 11.52, standoff -3.28, extent -86.298,-7.803 7.557,2.797
3D body: height 175.5, standoff 166.5, extent -92.287,-22.072 13.842,11.557
3D body: height 170, standoff 10, extent -90.658,-20.603 12.342,9.911
3D body: height 16, standoff 7, extent -92.258,-22.122 13.871,11.507

## CN_HDR1 [mm]
pads (1):
  rect 2x4 smd: 1(0,0)
Top Overlay:
  lines w0.254: -1.397,2.438 -1.397,3.886 1.422,3.886 1.422,2.438 -1.397,2.438
M13_Assembly_Info:
  lines w0.254: -0.432,-1.702 -0.432,9.322 0.406,9.322 0.406,-1.702 -0.432,-1.702
3D body: height 1, standoff 0, extent -0.432,-1.702 0.406,2.769
3D body: height 2.54, standoff 0, extent -1.397,2.438 1.422,3.912
3D body: height 1.9, standoff 0.9, extent -0.419,3.607 0.419,9.271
